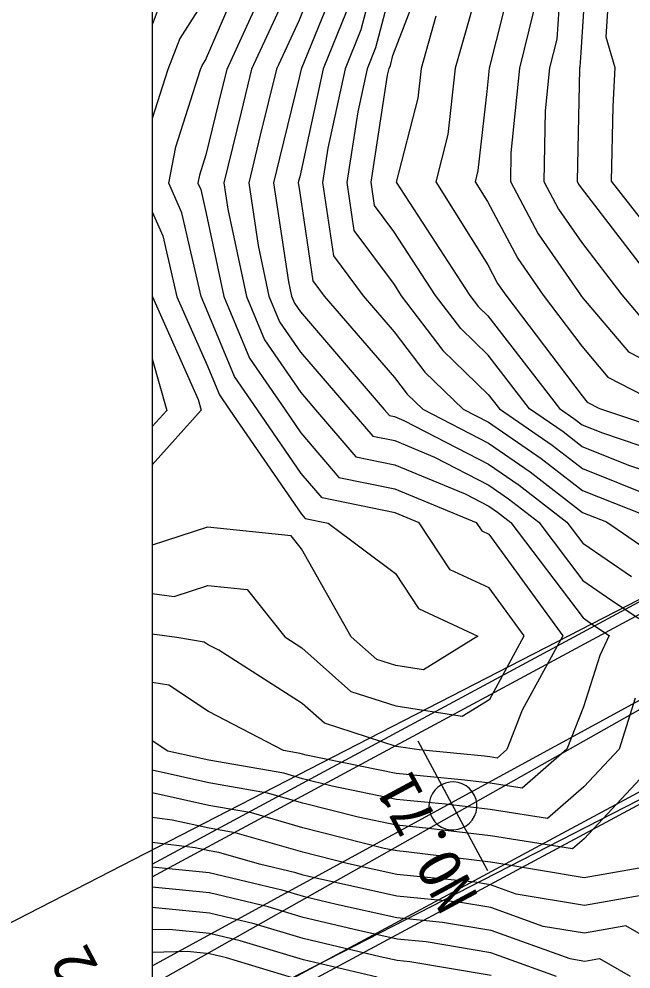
# Model space of a CAD drawing. Extents: x 42655 to 43811, y -141820 to -141156.
# Drawn here: x 42717.4 to 42750.6, y -141642.9 to -141591.3 of the extents above; entities that cross this region are included whole.
import ezdxf

# ---------------------------------------------------------------- set-up
doc = ezdxf.new("R2010")
doc.units = 0
for name, color, linetype in [('D-BMK-HTXT_1', 7, 'Continuous'), ('D-BMK_1', 7, 'Continuous'), ('D-STR-STR2トンネル', 7, 'Continuous'), ('D-TTL', 7, 'Continuous'), ('ZE_HICN', 7, 'Continuous'), ('ZE_LWCN', 7, 'Continuous'), ('着色', 7, 'Continuous')]:
    doc.layers.add(name, color=color, linetype=linetype)

msp = doc.modelspace()

# ---------------------------------------------------------------- linework, layer by layer
at = {"layer": 'D-BMK-HTXT_1'}
for p, q in [((42777.191, -141614.053), (42724.628, -141643.736)), ((42742.837, -141637.554), (42739.048, -141630.508))]:
    msp.add_line(p, q, dxfattribs=at)
msp.add_lwpolyline([(42739.643, -141634.031), (42739.663, -141634.263), (42739.725, -141634.488), (42739.827, -141634.698), (42739.964, -141634.886), (42740.132, -141635.048), (42740.326, -141635.176), (42740.541, -141635.268), (42740.768, -141635.319), (42741.001, -141635.33), (42741.232, -141635.299), (42741.453, -141635.227), (42741.659, -141635.116), (42741.841, -141634.971), (42741.994, -141634.795), (42742.114, -141634.595), (42742.196, -141634.377), (42742.237, -141634.148), (42742.237, -141633.915), (42742.196, -141633.685), (42742.114, -141633.467), (42741.994, -141633.267), (42741.841, -141633.092), (42741.659, -141632.946), (42741.453, -141632.836), (42741.232, -141632.764), (42741.001, -141632.732), (42740.768, -141632.743), (42740.541, -141632.795), (42740.326, -141632.886), (42740.132, -141633.015), (42739.964, -141633.176), (42739.827, -141633.364), (42739.725, -141633.574), (42739.663, -141633.799), (42739.643, -141634.031)], dxfattribs=at)
at = {"layer": 'D-BMK_1'}
msp.add_lwpolyline([(42724.628, -141642.707), (42777.191, -141614.053)], dxfattribs=at)
at = {"layer": 'D-STR-STR2トンネル'}
for points in [[(42724.628, -141637.196), (42756.158, -141620.2)], [(42724.628, -141637.875), (42756.447, -141620.726)], [(42724.628, -141647.478), (42760.547, -141628.171)], [(42724.628, -141648.156), (42760.837, -141628.697)]]:
    msp.add_lwpolyline(points, dxfattribs=at)
at = {"layer": 'D-TTL'}
msp.add_lwpolyline([(42724.63, -141820.399), (43685.83, -141820.386), (43685.821, -141155.586), (42724.621, -141155.599), (42724.63, -141820.399)], dxfattribs=at)
at = {"layer": 'ZE_HICN'}
for points in [[(42732.578, -141588.495), (42730.02, -141594.059), (42729.444, -141596.384), (42728.514, -141600.229), (42728.729, -141601.654), (42729.738, -141606.386), (42730.717, -141608.749), (42732.686, -141611.595), (42733.492, -141612.531), (42735.674, -141615.084), (42737.792, -141615.514), (42741.599, -141617.095), (42742.891, -141617.761), (42743.358, -141618.084), (42744.083, -141618.644), (42748.008, -141623.833), (42748.512, -141624.178), (42749.419, -141624.782), (42748.916, -141625.873), (42748.03, -141628.651), (42747.128, -141630.955), (42744.704, -141633.076), (42742.961, -141632.801), (42741.595, -141632.635), (42737.87, -141632.273), (42732.987, -141631.275), (42732.777, -141631.222), (42732.644, -141631.184), (42731.745, -141631.027), (42727.678, -141628.907), (42725.532, -141627.484), (42724.628, -141627.332)], [(42737.671, -141589.392), (42736.747, -141592.89), (42736.286, -141594.03), (42735.779, -141596.363), (42735.184, -141600.198), (42735.57, -141602.816), (42737.747, -141605.744), (42738.141, -141606.347), (42740.395, -141609.311), (42742.863, -141611.698), (42743.47, -141612.485), (42746.324, -141614.458), (42747.97, -141615.729), (42752.022, -141617.343)], [(42745.317, -141590.914), (42744.547, -141593.991), (42744.093, -141598.593), (42744.059, -141600.156), (42745.566, -141602.99), (42747.865, -141606.301), (42747.926, -141606.382), (42750.462, -141609.398), (42753.035, -141610.715)], [(42724.628, -141609.774), (42725.413, -141612.569), (42724.628, -141613.445)], [(42753.181, -141642.187), (42750.332, -141640.545), (42748.087, -141640.941), (42745.839, -141640.565), (42742.992, -141639.548), (42741.251, -141639.254), (42737.901, -141638.924), (42733.425, -141637.929), (42732.808, -141637.783), (42732.413, -141637.664), (42730.443, -141637.196), (42728.245, -141636.563), (42727.713, -141636.47), (42726.962, -141636.303), (42724.628, -141636.016)], [(42732.235, -141643.35), (42728.649, -141642.266), (42727.739, -141642.05), (42726.546, -141641.932), (42724.628, -141641.992)]]:
    msp.add_lwpolyline(points, dxfattribs=at)
at = {"layer": 'ZE_LWCN'}
for points in [[(42724.627, -141564.583), (42727.382, -141565.165), (42728.01, -141568.676), (42728.28, -141569.416), (42728.425, -141570.648), (42729.145, -141575.575), (42729.988, -141578.653), (42730.982, -141581.729), (42729.782, -141584.533), (42728.496, -141587.903), (42727.498, -141590.219), (42726.115, -141592.39), (42725.477, -141594.08), (42724.628, -141596.734), (42724.627, -141596.738)], [(42724.627, -141569.795), (42726.427, -141570.612), (42727.421, -141573.734), (42727.692, -141575.582), (42728.898, -141579.986), (42729.464, -141581.736), (42728.78, -141583.331), (42727.482, -141586.736), (42726.819, -141587.911), (42724.897, -141590.928), (42724.627, -141591.642)], [(42746.888, -141587.818), (42746.574, -141592.422), (42746.184, -141593.984), (42745.953, -141596.319), (42745.869, -141600.148), (42746.666, -141601.645), (42747.913, -141603.441), (42750.11, -141606.291), (42751.577, -141608.035)], [(42748.231, -141587.812), (42747.866, -141593.416), (42747.831, -141593.931), (42747.82, -141593.976), (42747.813, -141594.044), (42747.68, -141600.14), (42747.765, -141600.3), (42747.899, -141600.492), (42752.361, -141606.28)], [(42749.536, -141587.806), (42749.243, -141592.295), (42749.738, -141593.967), (42749.629, -141596.088), (42749.538, -141600.131), (42753.006, -141604.568)], [(42724.628, -141622.499), (42725.808, -141622.662), (42727.646, -141622.071), (42729.783, -141622.286), (42731.814, -141624.864), (42732.75, -141625.461), (42735.398, -141627.817), (42737.853, -141628.608), (42741.443, -141629.163), (42742.94, -141628.236), (42744.808, -141624.804), (42742.912, -141622.196), (42740.796, -141621.217), (42739.11, -141618.667), (42737.805, -141618.125), (42733.844, -141617.321), (42732.706, -141615.99), (42730.341, -141612.546), (42729.091, -141610.738), (42727.577, -141607.084), (42727.271, -141606.397), (42726.228, -141601.843), (42725.528, -141600.243), (42725.907, -141598.269), (42727.25, -141594.072), (42727.333, -141593.851), (42727.514, -141593.568), (42729.958, -141587.897)], [(42737.02, -141587.864), (42735.947, -141591.929), (42735.095, -141594.035), (42734.157, -141598.346), (42733.869, -141600.204), (42734.456, -141604.178), (42736.075, -141606.356), (42737.759, -141608.304), (42739.426, -141610.496), (42741.491, -141612.494), (42742.87, -141613.205), (42745.73, -141615.183), (42747.975, -141616.916), (42752.219, -141618.606)], [(42753.061, -141616.416), (42750.543, -141615.569), (42747.964, -141614.542), (42746.917, -141613.733), (42745.101, -141612.477), (42742.853, -141609.566), (42741.365, -141608.126), (42740.005, -141606.338), (42737.734, -141602.864), (42736.685, -141601.453), (42736.498, -141600.192), (42737.4, -141594.38), (42737.478, -141594.024), (42737.548, -141593.85), (42737.689, -141593.317), (42739.775, -141587.851)], [(42742.753, -141588.094), (42741.072, -141594.008), (42740.668, -141597.593), (42740.009, -141600.175), (42742.83, -141604.672), (42743.366, -141605.679), (42743.811, -141606.32), (42747.952, -141611.788), (42748.233, -141612.123), (42748.89, -141612.459), (42753.05, -141613.859)], [(42733.544, -141589.047), (42732.592, -141591.402), (42731.373, -141594.053), (42730.486, -141597.634), (42729.86, -141600.222), (42730.375, -141603.628), (42730.961, -141606.38), (42731.531, -141607.755), (42732.676, -141609.41), (42735.355, -141612.522), (42736.589, -141613.965), (42737.786, -141614.208), (42739.938, -141615.102), (42742.886, -141616.622), (42743.951, -141617.359), (42745.607, -141618.637), (42747.998, -141621.799), (42749.575, -141622.878), (42752.412, -141624.768)], [(42744.059, -141589.406), (42742.911, -141593.999), (42742.786, -141595.264), (42742.302, -141599.554), (42742.146, -141600.165), (42742.814, -141601.229), (42744.466, -141604.334), (42745.838, -141606.311), (42747.939, -141609.085), (42749.348, -141610.76), (42752.631, -141612.442)], [(42734.345, -141590.008), (42732.711, -141594.047), (42732.606, -141594.529), (42731.528, -141598.884), (42731.206, -141600.216), (42732.02, -141605.602), (42732.185, -141606.374), (42732.344, -141606.76), (42732.666, -141607.224), (42737.219, -141612.514), (42737.504, -141612.847), (42737.78, -141612.903), (42738.277, -141613.109), (42742.881, -141615.483), (42744.544, -141616.634), (42747.13, -141618.63), (42747.989, -141619.765), (42750.638, -141621.579)], [(42730.138, -141590.864), (42728.666, -141594.065), (42728.402, -141595.133), (42727.538, -141598.706), (42727.187, -141599.804), (42727.104, -141600.235), (42727.257, -141600.585), (42727.552, -141601.877), (42728.515, -141606.391), (42729.904, -141609.744), (42731.837, -141612.539), (42732.696, -141613.789), (42734.759, -141616.203), (42737.798, -141616.82), (42742.213, -141618.653), (42742.517, -141619.113), (42742.898, -141619.289), (42746.902, -141624.794), (42744.702, -141628.836), (42743.866, -141630.971), (42743.336, -141631.435), (42742.954, -141631.374), (42742.656, -141631.338), (42739.102, -141630.993), (42737.863, -141630.801), (42733.981, -141629.549), (42732.764, -141628.467), (42728.246, -141625.587), (42727.661, -141625.282), (42727.449, -141625.141), (42725.963, -141624.891), (42724.628, -141624.706)], [(42735.146, -141590.968), (42733.903, -141594.041), (42732.631, -141599.888), (42732.57, -141600.135), (42732.552, -141600.21), (42732.635, -141600.761), (42733.341, -141605.541), (42733.955, -141606.366), (42737.77, -141610.779), (42738.457, -141611.681), (42739.307, -141612.504), (42742.875, -141614.344), (42745.137, -141615.908), (42747.981, -141618.104), (42749.278, -141618.62), (42751.7, -141620.279)], [(42740.023, -141591.174), (42739.215, -141594.016), (42739.033, -141595.632), (42737.871, -141600.185), (42738.328, -141600.914), (42741.869, -141606.329), (42742.334, -141606.941), (42742.843, -141607.434), (42746.732, -141612.469), (42747.51, -141613.008), (42747.959, -141613.354), (42749.064, -141613.794), (42753.055, -141615.138)], [(42724.627, -141601.791), (42725.2, -141603.1), (42725.956, -141606.403), (42727.59, -141610.075), (42728.277, -141611.733), (42728.844, -141612.553), (42732.717, -141618.191), (42732.929, -141618.44), (42734.164, -141618.69), (42737.82, -141621.423), (42739.075, -141623.321), (42742.303, -141624.815), (42739.346, -141626.648), (42737.843, -141626.415), (42736.815, -141626.084), (42735.426, -141624.847), (42732.725, -141620.073), (42732.17, -141619.368), (42727.632, -141618.91), (42724.628, -141619.877)], [(42724.627, -141606.349), (42724.641, -141606.409), (42727.121, -141611.982), (42727.284, -141612.56), (42724.628, -141615.524)], [(42750.84, -141628.181), (42749.959, -141630.942), (42748.05, -141632.987), (42746.072, -141634.717), (42742.968, -141634.227), (42740.534, -141633.932), (42737.877, -141633.674), (42734.393, -141632.962), (42732.783, -141632.553), (42731.764, -141632.26), (42727.69, -141631.55), (42725.469, -141631.056), (42724.628, -141630.499)], [(42752.623, -141630.93), (42748.063, -141635.813), (42747.44, -141636.359), (42742.974, -141635.654), (42739.474, -141635.229), (42737.883, -141635.074), (42735.799, -141634.648), (42732.79, -141633.884), (42730.884, -141633.335), (42727.696, -141632.78), (42724.628, -141632.098)], [(42752.807, -141637.092), (42748.073, -141637.927), (42743.332, -141637.136), (42742.981, -141637.08), (42738.413, -141636.526), (42737.89, -141636.475), (42737.204, -141636.335), (42732.796, -141635.215), (42730.004, -141634.411), (42727.702, -141634.01), (42724.628, -141633.327)], [(42751.774, -141638.782), (42748.08, -141639.434), (42744.381, -141638.816), (42742.987, -141638.318), (42742.134, -141638.174), (42737.896, -141637.756), (42735.272, -141637.173), (42732.802, -141636.546), (42729.125, -141635.487), (42727.708, -141635.24), (42725.705, -141634.795), (42724.628, -141634.663)], [(42724.628, -141637.342), (42727.719, -141637.649), (42731.66, -141638.584), (42732.813, -141638.932), (42734.618, -141639.36), (42737.907, -141640.091), (42740.368, -141640.333), (42742.998, -141640.778), (42747.296, -141642.314), (42748.094, -141642.448), (42748.891, -141642.307), (42750.553, -141643.265)], [(42746.572, -141643.283), (42743.004, -141642.008), (42739.485, -141641.413), (42737.912, -141641.258), (42735.811, -141640.791), (42732.818, -141640.082), (42730.908, -141639.505), (42727.724, -141638.749), (42724.628, -141638.442)], [(42743.01, -141643.239), (42738.602, -141642.492), (42737.918, -141642.425), (42737.003, -141642.222), (42732.824, -141641.232), (42730.155, -141640.425), (42727.729, -141639.85), (42724.628, -141639.542)], [(42736.828, -141643.329), (42732.829, -141642.382), (42729.402, -141641.346), (42727.734, -141640.95), (42725.547, -141640.733), (42724.628, -141640.762)]]:
    msp.add_lwpolyline(points, dxfattribs=at)
at = {"layer": '着色'}
for points in [[(42654.785, -141672.308), (42756.158, -141620.2)], [(42760.837, -141628.697), (42654.786, -141683.055)]]:
    msp.add_lwpolyline(points, dxfattribs=at)

# ---------------------------------------------------------------- texts
at = {"layer": 'D-BMK-HTXT_1'}
for s, rotation, p in [('NO.71', 118.2676, (42742.364, -141638.944)), ('NO.72', 117.6947, (42724.653, -141648.342))]:
    msp.add_text(s, height=2.3065, rotation=rotation, dxfattribs=at).set_placement(p)

doc.saveas('drawing.dxf')
